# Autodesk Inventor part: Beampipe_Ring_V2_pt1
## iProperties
Shininess: 64.0
Length Units: 11269
Angle Units: 11279
Time Units: 11290
Mass Units: 11283
Length Display Precision: 3
Angle Display Precision: 2
Compacted: True
Part Number: Beampipe_Ring_V2_pt1
Document SubType Name: Modeling
Created: 2004-08
Designer: John Blackburn
Manufacturer: Standard
Standards Organization: Custom
Material: Aluminum-6061
Density: 0.0
Volumn: 0.0
Area: 0.0
PropertySet Name: Model Information
Control State: 0
Master: False
Checked Out: False
Author: John Blackburn
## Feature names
1. Extrusion1
2. Extrusion3
3. Split1
4. Hole6
5. Hole7
6. Hole8
7. Circular Pattern1
8. Hole10
9. Extrusion8
10. Extrusion9
